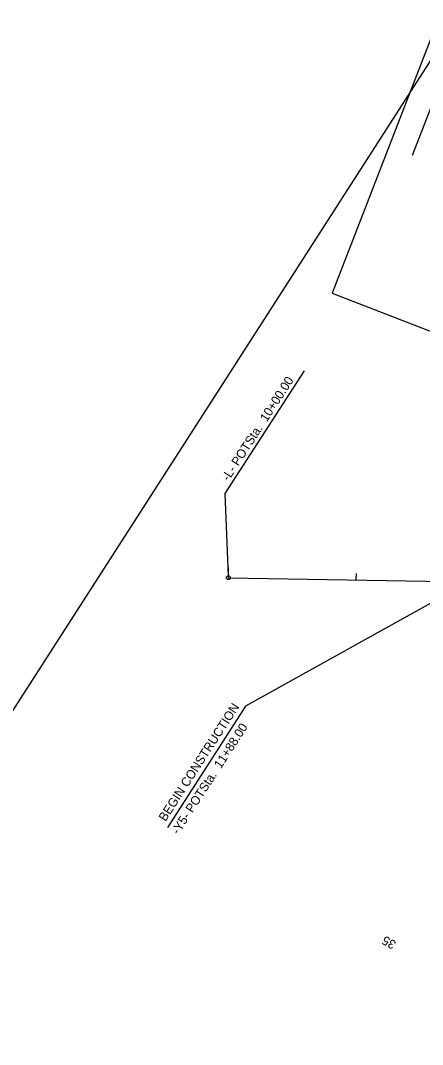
# Model space of a CAD drawing. Extents: x 1974386 to 1979988, y 776712 to 784860.
# Drawn here: x 1976659 to 1976973, y 780494 to 781294 of the extents above; entities that cross this region are included whole.
import ezdxf

# ---------------------------------------------------------------- set-up
doc = ezdxf.new("R2010")
doc.units = 0
for name, color, linetype in [('Prop Horizontal Alignment', 7, 'Continuous'), ('Prop Horizontal Alignment Station Label', 7, 'Continuous'), ('Prop Horizontal Alignment Tick Label', 7, 'Continuous'), ('Prop Horizontal Alignment Tick Large', 7, 'Continuous'), ('Prop Horizontal Alignment Tick Small', 7, 'Continuous'), ('Sheet Layout Plan Border', 7, 'Continuous')]:
    doc.layers.add(name, color=color, linetype=linetype)

msp = doc.modelspace()

# ---------------------------------------------------------------- linework, layer by layer
at = {"layer": 'Prop Horizontal Alignment'}
msp.add_line((1976821.75, 780858.8), (1977201.14, 780852.41), dxfattribs=at)
at = {"layer": 'Prop Horizontal Alignment Station Label'}
for p, q in [((1976965.67, 781189.17), (1977012.65, 781310.45)), ((1976819.36, 780924.7), (1976881.34, 781020.58)), ((1976821.77, 780860.3), (1976819.36, 780924.7)), ((1977009.72, 780855.64), (1976835.21, 780758.48)), ((1976835.21, 780758.48), (1976774.07, 780663.66))]:
    msp.add_line(p, q, dxfattribs=at)
msp.add_circle((1976821.75, 780858.8), 1.5, dxfattribs=at)
at = {"layer": 'Prop Horizontal Alignment Tick Large'}
msp.add_line((1976821.75, 780858.8), (1976821.88, 780866.8), dxfattribs=at)
at = {"layer": 'Prop Horizontal Alignment Tick Small'}
msp.add_line((1976921.73, 780857.12), (1976921.82, 780862.12), dxfattribs=at)
at = {"layer": 'Sheet Layout Plan Border'}
for points in [[(1977881.86, 780701.89), (1978387.67, 782007.32), (1977408.59, 782386.68), (1976902.78, 781081.25)], [(1977111.11, 779526.05), (1977868.38, 780703.57), (1976985.24, 781271.52), (1976227.97, 780094)]]:
    msp.add_lwpolyline(points, close=True, dxfattribs=at)

# ---------------------------------------------------------------- texts
at = {"layer": 'Prop Horizontal Alignment Station Label'}
for s, p in [('-L- POTSta.  10+00.00', (1976821.85, 780933.77)), ('BEGIN CONSTRUCTION', (1976772.61, 780667.79)), ('-Y5- POTSta.  11+88.00', (1976782.61, 780657.5))]:
    msp.add_text(s, height=7, rotation=57.18801, dxfattribs=at).set_placement(p)
at = {"layer": 'Prop Horizontal Alignment Tick Label'}
msp.add_text('35', height=7, rotation=150.55025, dxfattribs=at).set_placement((1976953.44, 780574.1))

doc.saveas('drawing.dxf')
